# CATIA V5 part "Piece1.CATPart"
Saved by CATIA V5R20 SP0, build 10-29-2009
Part number: Piece1
Bounding box of the stored display mesh (mm): x 0 to 100, y -50 to 0, z 0 to 86.603
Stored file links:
  C:\Users\Lambert\Desktop\IAO\Piece1.CATPart
  C:\Users\Lambert\Desktop\IAO\Produit1.CATProduct
  C:\Users\Lambert\Desktop\IAO\skl_general.CATPart
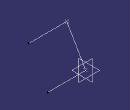
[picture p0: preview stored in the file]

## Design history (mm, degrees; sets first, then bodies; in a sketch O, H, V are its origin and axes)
Set1
  Line1 "Bielle 1": type PtPt, FirstPoint Point1, SecondPoint Point2, Support Plane1
  Line2 "Axe_pivot_10": type Normal, RefPoint Point2, RefSkin Plane1, Start 0, End 100
  Line3 "Axe_pivot_12": type Normal, RefPoint Point1, RefSkin Plane1, Start 0, End 100
Set2
  Point1 "B": linked copy from another document
  Point2 "A": linked copy from another document
  Plane1 "Plan_Ref": linked copy from another document
Body1 (main body)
